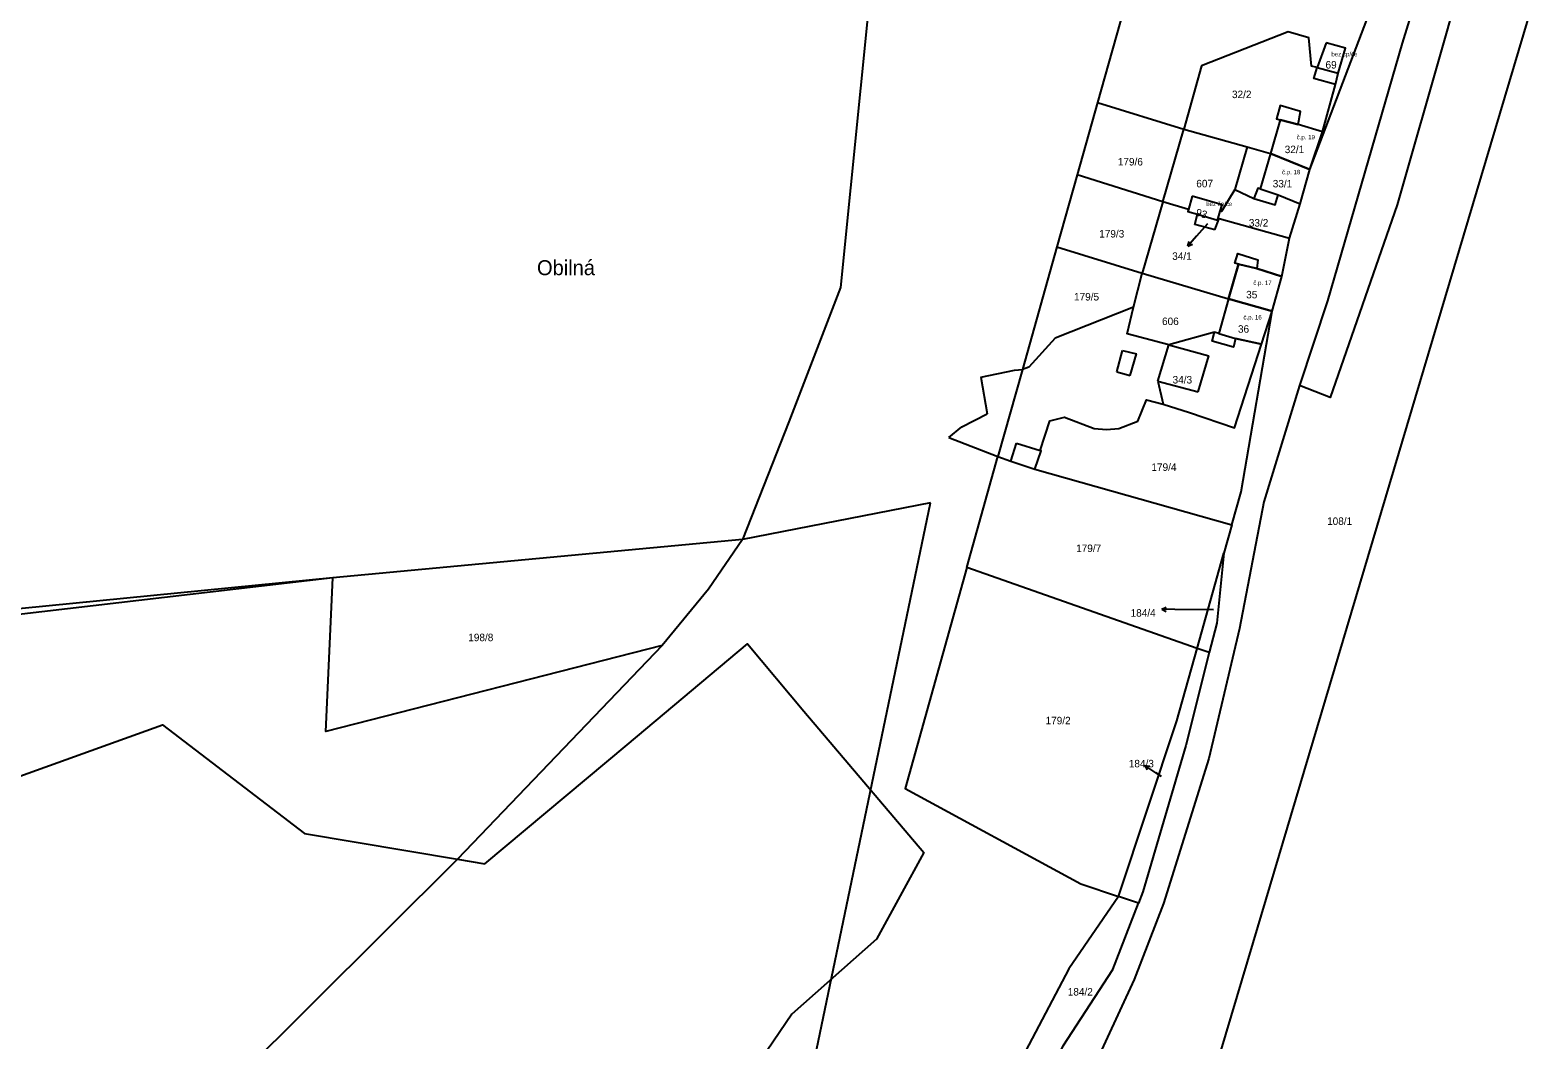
# Model space of a CAD drawing. Extents: x -882150 to -879379, y -1022570 to -1019819.
# Drawn here: x -880457.2 to -880115.3, y -1020677.8 to -1020448.8 of the extents above; entities that cross this region are included whole.
import ezdxf

# ---------------------------------------------------------------- set-up
doc = ezdxf.new("R2010")
doc.units = 0
for name, color, linetype in [('Definiční body', 7, 'Continuous'), ('Hranice parcel', 7, 'Continuous'), ('Parcelní čísla', 7, 'Continuous'), ('Polygon budovy', 7, 'Continuous'), ('Pop  PČ popisy', 7, 'Continuous'), ('Vnitřní kresba', 7, 'Continuous')]:
    doc.layers.add(name, color=color, linetype=linetype)

msp = doc.modelspace()

# ---------------------------------------------------------------- linework, layer by layer
at = {"layer": 'Hranice parcel'}
for p, q in [((-880206.12, -1020433.27), (-880215.14, -1020465.24)), ((-880167, -1020480.4), (-880154.08, -1020446.48)), ((-880163.32, -1020451.73), (-880165.32, -1020457.28)), ((-880158.94, -1020452.94), (-880163.32, -1020451.73)), ((-880164.16, -1020471.89), (-880161.19, -1020461.12)), ((-880215.14, -1020465.24), (-880219.75, -1020481.6)), ((-880215.14, -1020465.24), (-880195.59, -1020471.28)), ((-880200.33, -1020487.77), (-880195.59, -1020471.28)), ((-880195.59, -1020471.28), (-880181.18, -1020475.3)), ((-880164.16, -1020471.89), (-880169.65, -1020470.2)), ((-880167, -1020480.4), (-880164.16, -1020471.89)), ((-880181.18, -1020475.3), (-880175.92, -1020476.82)), ((-880175.92, -1020476.82), (-880167, -1020480.4)), ((-880219.75, -1020481.6), (-880224.36, -1020497.97)), ((-880200.33, -1020487.77), (-880219.75, -1020481.6)), ((-880169.2, -1020488.2), (-880167, -1020480.4)), ((-880200.33, -1020487.77), (-880204.99, -1020503.95)), ((-880194.55, -1020489.46), (-880200.33, -1020487.77)), ((-880193.7, -1020486.5), (-880194.55, -1020489.46)), ((-880186.92, -1020488.46), (-880193.7, -1020486.5)), ((-880187.34, -1020489.89), (-880186.92, -1020488.46)), ((-880174.17, -1020486.18), (-880169.2, -1020488.2)), ((-880171.61, -1020496.01), (-880169.2, -1020488.2)), ((-880194.55, -1020489.46), (-880194.69, -1020489.92)), ((-880187.91, -1020491.88), (-880187.79, -1020491.45)), ((-880187.79, -1020491.45), (-880187.34, -1020489.89)), ((-880224.36, -1020497.97), (-880232.17, -1020525.76)), ((-880224.36, -1020497.97), (-880204.99, -1020503.95)), ((-880173.36, -1020504.66), (-880171.61, -1020496.01)), ((-880206.96, -1020511.65), (-880204.99, -1020503.95)), ((-880204.99, -1020503.95), (-880185.42, -1020509.79)), ((-880175.57, -1020512.55), (-880173.36, -1020504.66)), ((-880185.42, -1020509.79), (-880175.57, -1020512.55)), ((-880177.99, -1020520.07), (-880175.57, -1020512.55)), ((-880232.17, -1020525.76), (-880237.77, -1020545.51)), ((-880244.8, -1020570.65), (-880237.77, -1020545.51)), ((-880229.35, -1020548.34), (-880184.68, -1020560.98)), ((-880295.63, -1020564.31), (-880388.55, -1020572.98)), ((-880184.68, -1020560.98), (-880186.5, -1020567.4)), ((-880192.56, -1020589.01), (-880186.5, -1020567.4)), ((-880192.56, -1020589.01), (-880244.8, -1020570.65)), ((-880313.84, -1020588.35), (-880360.27, -1020636.82)), ((-880189.82, -1020589.97), (-880192.56, -1020589.01)), ((-880205.85, -1020646.77), (-880210.36, -1020645.27))]:
    msp.add_line(p, q, dxfattribs=at)
for points in [[(-880045.71, -1020206.44), (-880072.78, -1020243.25), (-880109.94, -1020357.24), (-880136.37, -1020450.63), (-880147.18, -1020488.43), (-880162.39, -1020532.15), (-880169.37, -1020529.41)], [(-880077.54, -1020210.05), (-880083.07, -1020241.93), (-880088.6, -1020266), (-880146.1, -1020451.8), (-880163.01, -1020510.18), (-880169.37, -1020529.41)], [(-880181.75, -1020778.37), (-880224.49, -1020805.59), (-880179.88, -1020655.79), (-880135.29, -1020506), (-880090.68, -1020356.2)], [(-880224.37, -1020419.46), (-880231.68, -1020412.27), (-880243.47, -1020406.04), (-880262.13, -1020422.22), (-880266.61, -1020439.29), (-880273.4, -1020507.16), (-880285.17, -1020537.62), (-880295.63, -1020564.31)], [(-880165.32, -1020457.28), (-880166.64, -1020457.03), (-880167.2, -1020450.56), (-880171.91, -1020449.18), (-880191.6, -1020456.9), (-880195.59, -1020471.28)], [(-880161.19, -1020461.12), (-880160.58, -1020458.58), (-880158.94, -1020452.94)], [(-880161.19, -1020461.12), (-880166.1, -1020459.81), (-880165.32, -1020457.28)], [(-880169.65, -1020470.2), (-880169.1, -1020467.3), (-880173.74, -1020465.89), (-880174.53, -1020468.94), (-880173.7, -1020469.17), (-880175.92, -1020476.82)], [(-880181.18, -1020475.3), (-880184.02, -1020484.93), (-880187.05, -1020489.98), (-880187.34, -1020489.89)], [(-880175.92, -1020476.82), (-880178.24, -1020484.82), (-880178.8, -1020484.68), (-880179.69, -1020487.01), (-880174.89, -1020488.43), (-880174.17, -1020486.18)], [(-880194.69, -1020489.92), (-880192.49, -1020490.55), (-880187.91, -1020491.88)], [(-880187.79, -1020491.45), (-880187.55, -1020491.52), (-880171.61, -1020496.01)], [(-880185.42, -1020509.79), (-880183.2, -1020501.9), (-880184.04, -1020501.67), (-880183.31, -1020499.45), (-880178.76, -1020500.91), (-880179, -1020502.9), (-880173.36, -1020504.66)], [(-880206.96, -1020511.65), (-880224.73, -1020518.66), (-880230.72, -1020525.25), (-880232.17, -1020525.76)], [(-880188.62, -1020517.31), (-880198.95, -1020520.21), (-880208.43, -1020517.69), (-880206.96, -1020511.65)], [(-880185.42, -1020509.79), (-880187.63, -1020517.63), (-880188.62, -1020517.31)], [(-880184.68, -1020560.98), (-880182.56, -1020553.5), (-880175.57, -1020512.55)], [(-880177.99, -1020520.07), (-880183.87, -1020518.77), (-880184.34, -1020520.71), (-880189.18, -1020519.37), (-880188.62, -1020517.31)], [(-880229.35, -1020548.34), (-880227.89, -1020544.19), (-880228.19, -1020544.14), (-880225.94, -1020537.38), (-880222.63, -1020536.58), (-880215.89, -1020539.15), (-880213.13, -1020539.41), (-880210.28, -1020539.13), (-880206.01, -1020537.46), (-880204.06, -1020532.65), (-880200.29, -1020533.66), (-880194.27, -1020535.56), (-880184.06, -1020538.99), (-880177.99, -1020520.07)], [(-880169.37, -1020529.41), (-880177.43, -1020555.79), (-880182.92, -1020584.5), (-880189.9, -1020614), (-880200.18, -1020646.83), (-880206.84, -1020664.08), (-880223.08, -1020699.25), (-880243.38, -1020747.4), (-880257.98, -1020793.2), (-880271.05, -1020822.37), (-880283.1, -1020854.61), (-880286.7, -1020865.81)], [(-880237.77, -1020545.51), (-880234.77, -1020546.57), (-880229.35, -1020548.34)], [(-880295.63, -1020564.31), (-880303.33, -1020575.61), (-880313.84, -1020588.35)], [(-880186.5, -1020567.4), (-880188.13, -1020583.28), (-880189.82, -1020589.97)], [(-880244.8, -1020570.65), (-880258.8, -1020620.75), (-880218.96, -1020642.42), (-880210.36, -1020645.27)], [(-880388.55, -1020572.98), (-880500.39, -1020584.08), (-880515.21, -1020588.29), (-880628.31, -1020656.5), (-880820.82, -1020762.82)], [(-880313.84, -1020588.35), (-880390.12, -1020607.88), (-880388.55, -1020572.98)], [(-880360.27, -1020636.82), (-880354.1, -1020637.87), (-880321.84, -1020610.85), (-880294.54, -1020587.99), (-880281.75, -1020603.26), (-880254.56, -1020635.3), (-880265.26, -1020654.96), (-880284.47, -1020671.92), (-880292.9, -1020684.4), (-880298.58, -1020723.73), (-880329.61, -1020741.11), (-880349.9, -1020777.37), (-880372.99, -1020821.6), (-880387.98, -1020873.06), (-880446.75, -1020856.01), (-880505.51, -1020841.96)], [(-880210.36, -1020645.27), (-880197.17, -1020605.46), (-880192.56, -1020589.01)], [(-880189.82, -1020589.97), (-880195.12, -1020611.03), (-880204.86, -1020644.21), (-880205.85, -1020646.77)], [(-880505.51, -1020841.96), (-880518.42, -1020838.87), (-880598.48, -1020816.02), (-880668.07, -1020794.46), (-880662.34, -1020782.6), (-880663.62, -1020755.13), (-880652.38, -1020739.25), (-880665.62, -1020711.65), (-880647.59, -1020705.66), (-880571.11, -1020664.04), (-880510.86, -1020625.14), (-880461.45, -1020618.69), (-880427.21, -1020606.31), (-880394.95, -1020630.96), (-880360.27, -1020636.82)], [(-880360.27, -1020636.82), (-880459.8, -1020735.88), (-880505.51, -1020841.96)], [(-880210.36, -1020645.27), (-880221.64, -1020661.69), (-880238.27, -1020693.28)], [(-880231.63, -1020698.12), (-880222.93, -1020679.1), (-880211.66, -1020661.81), (-880205.85, -1020646.77)]]:
    msp.add_lwpolyline(points, dxfattribs=at)
at = {"layer": 'Polygon budovy'}
for points in [[(-880163.32, -1020451.73), (-880165.32, -1020457.28), (-880160.58, -1020458.58), (-880158.94, -1020452.94)], [(-880169.65, -1020470.2), (-880173.7, -1020469.17), (-880175.92, -1020476.82), (-880167, -1020480.4), (-880164.16, -1020471.89)], [(-880175.92, -1020476.82), (-880178.24, -1020484.82), (-880174.17, -1020486.18), (-880169.2, -1020488.2), (-880167, -1020480.4)], [(-880193.7, -1020486.5), (-880194.55, -1020489.46), (-880194.69, -1020489.92), (-880192.49, -1020490.55), (-880187.91, -1020491.88), (-880187.79, -1020491.45), (-880187.34, -1020489.89), (-880186.92, -1020488.46)], [(-880185.42, -1020509.79), (-880175.57, -1020512.55), (-880173.36, -1020504.66), (-880179, -1020502.9), (-880183.2, -1020501.9)], [(-880185.42, -1020509.79), (-880187.63, -1020517.63), (-880183.87, -1020518.77), (-880177.99, -1020520.07), (-880175.57, -1020512.55)]]:
    msp.add_lwpolyline(points, close=True, dxfattribs=at)
at = {"layer": 'Pop  PČ popisy'}
for p, q in [((-880192.68, -1020495.57), (-880194.688, -1020497.8)), ((-880190.18, -1020492.78), (-880192.68, -1020495.57)), ((-880194.688, -1020497.8), (-880194.39, -1020496.721)), ((-880194.688, -1020497.8), (-880193.646, -1020497.391)), ((-880200.601, -1020580.138), (-880199.59, -1020579.654)), ((-880197.6, -1020580.19), (-880200.601, -1020580.138)), ((-880200.601, -1020580.138), (-880199.608, -1020580.656)), ((-880188.86, -1020580.29), (-880197.6, -1020580.19)), ((-880201.92, -1020617.22), (-880204.408, -1020615.542)), ((-880204.408, -1020615.542), (-880203.298, -1020615.687)), ((-880204.408, -1020615.542), (-880203.858, -1020616.517)), ((-880200.63, -1020618.08), (-880201.92, -1020617.22))]:
    msp.add_line(p, q, dxfattribs=at)
at = {"layer": 'Vnitřní kresba'}
for p, q in [((-880165.32, -1020457.28), (-880160.58, -1020458.58)), ((-880173.7, -1020469.17), (-880169.65, -1020470.2)), ((-880184.02, -1020484.93), (-880179.69, -1020487.01)), ((-880178.24, -1020484.82), (-880174.17, -1020486.18)), ((-880193.08, -1020492.88), (-880192.49, -1020490.55)), ((-880188.52, -1020494.09), (-880187.55, -1020491.52)), ((-880188.52, -1020494.09), (-880193.08, -1020492.88)), ((-880183.2, -1020501.9), (-880179, -1020502.9)), ((-880187.63, -1020517.63), (-880183.87, -1020518.77)), ((-880210.79, -1020526.29), (-880209.49, -1020521.49)), ((-880209.49, -1020521.49), (-880206.31, -1020522.25)), ((-880207.74, -1020527.17), (-880206.31, -1020522.25)), ((-880201.45, -1020528.4), (-880198.95, -1020520.21)), ((-880198.95, -1020520.21), (-880189.94, -1020522.67)), ((-880192.29, -1020530.87), (-880189.94, -1020522.67)), ((-880241.6, -1020527.54), (-880234.01, -1020525.94)), ((-880234.01, -1020525.94), (-880232.17, -1020525.76)), ((-880210.79, -1020526.29), (-880207.74, -1020527.17)), ((-880241.6, -1020527.54), (-880240.14, -1020535.81)), ((-880201.45, -1020528.4), (-880192.29, -1020530.87)), ((-880201.45, -1020528.4), (-880200.29, -1020533.66)), ((-880245.94, -1020538.79), (-880240.14, -1020535.81)), ((-880248.87, -1020541.2), (-880245.94, -1020538.79)), ((-880248.87, -1020541.2), (-880237.77, -1020545.51)), ((-880234.77, -1020546.57), (-880233.54, -1020542.45)), ((-880233.54, -1020542.45), (-880228.19, -1020544.14)), ((-880328, -1020916), (-880253, -1020556)), ((-880253, -1020556), (-880295.63, -1020564.31)), ((-880295.63, -1020564.31), (-880388.55, -1020572.98)), ((-880388.55, -1020572.98), (-880508, -1020587))]:
    msp.add_line(p, q, dxfattribs=at)

# ---------------------------------------------------------------- texts
at = {"layer": 'Definiční body'}
for s, p in [('bez čp/če', (-880162.11, -1020454.78)), ('č.p. 19', (-880169.99, -1020473.58)), ('č.p. 18', (-880173.31, -1020481.51)), ('bez čp/če', (-880190.5, -1020488.72)), ('č.p. 17', (-880179.82, -1020506.63)), ('č.p. 16', (-880182.06, -1020514.44))]:
    msp.add_text(s, height=1, dxfattribs=at).set_placement(p)
at = {"layer": 'Parcelní čísla'}
for s, p in [('69', (-880163.45, -1020457.54)), ('32/2', (-880184.66, -1020464.24)), ('32/1', (-880172.7, -1020476.72)), ('179/6', (-880210.55, -1020479.52)), ('607', (-880192.75, -1020484.47)), ('33/1', (-880175.41, -1020484.49)), ('33/2', (-880180.84, -1020493.37)), ('179/3', (-880214.77, -1020495.85)), ('34/1', (-880198.208, -1020500.91)), ('179/5', (-880220.48, -1020510.13)), ('35', (-880181.44, -1020509.65)), ('606', (-880200.52, -1020515.7)), ('36', (-880183.3, -1020517.44)), ('34/3', (-880198.12, -1020528.95)), ('179/4', (-880202.93, -1020548.77)), ('108/1', (-880163.09, -1020561.02)), ('179/7', (-880220, -1020567.17)), ('184/4', (-880207.649, -1020581.82)), ('198/8', (-880357.84, -1020587.38)), ('179/2', (-880226.927, -1020606.23)), ('184/3', (-880208.056, -1020615.99)), ('184/2', (-880221.9, -1020667.73))]:
    msp.add_text(s, height=1.7, dxfattribs=at).set_placement(p)
msp.add_text('93', height=1.7, rotation=344, dxfattribs=at).set_placement((-880193.013, -1020490.879))
at = {"layer": 'Pop  PČ popisy'}
msp.add_text('Obilná', height=3.4, dxfattribs=at).set_placement((-880342.25, -1020504.39))

doc.saveas('drawing.dxf')
